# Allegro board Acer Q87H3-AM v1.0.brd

Outline 244 x 244 mm; copper layers: TOP, PWR, GND, BOTTOM. Coordinates in mm from the lower left corner of the outline.
Outline path: 0,240.95 arc(0.89,243.11) 3.05,244 240.95,244 arc(243.11,243.11) 244,240.95 244,3.05 arc(243.11,0.89) 240.95,0 3.05,0 arc(0.89,0.89) 0,3.05 0,240.95

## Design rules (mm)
net group DIFFPAIR133: nets M_CLK_A_N3 M_CLK_A_P3
net group DIFFPAIR134: nets M_CLK_A_N2 M_CLK_A_P2
net group DIFFPAIR135: nets M_CLK_A_N1 M_CLK_A_P1
net group DIFFPAIR136: nets M_CLK_A_N0 M_CLK_A_P0
net group DIFFPAIR197: nets DDIB_AUX_N DDIB_AUX_P
net group DIFFPAIR198: nets DDIB_AUXN DDIB_AUXP
net group DIFFPAIR199: nets DDIB_AUXN_C DDIB_AUXP_C
net group DIFFPAIR237: nets USB_N10 USB_P10
net group DIFFPAIR245: nets BRIDGE_CLK_N BRIDGE_CLK_P
net group DIFFPAIR256: nets USB+12 USB-12
net group DIFFPAIR257: nets USB+13 USB-13
net group DIFFPAIR259: nets DDIC_N0_R DDIC_P0_R
net group DIFFPAIR260: nets DDIC_N1_R DDIC_P1_R
net group DIFFPAIR261: nets DDIC_N2_R DDIC_P2_R
net group DIFFPAIR262: nets DDIC_N3_R DDIC_P3_R
net group DIFFPAIR264: nets ISEN1_3 V3N
net group DIFFPAIR265: nets ISEN1_2 V2N
net group DIFFPAIR266: nets ISEN1_1 V1N
net group DIFFPAIR267: nets ISEN1_4 V4N
net group DIFFPAIR269: nets SATA3_TX_N1_C SATA3_TX_P1_C
net group DIFFPAIR270: nets SATA3_RX_N1_C SATA3_RX_P1_C
net group DIFFPAIR271: nets SATA3_TX_N3_C SATA3_TX_P3_C
net group DIFFPAIR272: nets SATA3_RX_N3_C SATA3_RX_P3_C
net group DIFFPAIR273: nets SATA3_TX_N0_C SATA3_TX_P0_C
net group DIFFPAIR274: nets SATA3_RX_N0_C SATA3_RX_P0_C
net group DIFFPAIR275: nets SATA3_TX_N2_C SATA3_TX_P2_C
net group DIFFPAIR276: nets SATA3_RX_N2_C SATA3_RX_P2_C
net group DIFFPAIR277: nets +VCC_CSN2 +VCC_CSP2
net group DIFFPAIR278: nets +VCC3_CSN1 +VCC3_CSP1
net group DIFFPAIR279: nets DDIC_AUXN DDIC_AUXP
net group DIFFPAIR280: nets USB+3 USB-3
net group DIFFPAIR281: nets ILAN_TXN_C ILAN_TXP_C
net group DIFFPAIR282: nets ILAN_RXN_C ILAN_RXP_C
net group DIFFPAIR283: nets BRIDGE_TX_N2 BRIDGE_TX_P2
net group DIFFPAIR284: nets BRIDGE_TX_N2_C BRIDGE_TX_P2_C
net group DIFFPAIR285: nets BRIDGE_RX_N2_C BRIDGE_RX_P2_C
net group DIFFPAIR286: nets BRIDGE_RX_N2 BRIDGE_RX_P2
net group DIFFPAIR287: nets DDIC_AUX_N DDIC_AUX_P
net group DIFFPAIR288: nets RLAN_RXN_C RLAN_RXP_C
net group DIFFPAIR289: nets RLAN_TXN_C RLAN_TXP_C
net group DIFFPAIR292: nets SATA3_RX_N4_C SATA3_RX_P4_C
net group DIFFPAIR293: nets SATA3_TX_N4_C SATA3_TX_P4_C
net group DIFFPAIR294: nets SATA3_RX_N4 SATA3_RX_P4
net group DIFFPAIR295: nets SATA3_TX_N4 SATA3_TX_P4
net group DIFFPAIR296: nets DDIC_AUXN_C DDIC_AUXP_C
net group G1_UG: nets G1_UG G1_UG_R
net group G2_UG: nets G2_UG G2_UG_R
net group G3_UG: nets G3_UG G3_UG_R
net group DDR_DQS_A: nets M_DQS_A_N0 M_DQS_A_N1 M_DQS_A_N2 M_DQS_A_N3 M_DQS_A_N4 M_DQS_A_N5 M_DQS_A_N6 M_DQS_A_N7 M_DQS_A_P0 M_DQS_A_P1 M_DQS_A_P2 M_DQS_A_P3 M_DQS_A_P4 M_DQS_A_P5 M_DQS_A_P6 M_DQS_A_P7
net group DDR_DQS_B: nets M_DQS_B_N0 M_DQS_B_N1 M_DQS_B_N2 M_DQS_B_N3 M_DQS_B_N4 M_DQS_B_N5 M_DQS_B_N6 M_DQS_B_N7 M_DQS_B_P0 M_DQS_B_P1 M_DQS_B_P2 M_DQS_B_P3 M_DQS_B_P4 M_DQS_B_P5 M_DQS_B_P6 M_DQS_B_P7
net group DDRCLK-B: nets M_CLK_B_N0 M_CLK_B_N1 M_CLK_B_N2 M_CLK_B_N3 M_CLK_B_P0 M_CLK_B_P1 M_CLK_B_P2 M_CLK_B_P3
net group DDRCMD-A: nets M_BS_A0 M_BS_A1 M_BS_A2 M_CAS_A_L M_MA_A0 M_MA_A1 M_MA_A2 M_MA_A3 M_MA_A4 M_MA_A5 M_MA_A6 M_MA_A7 M_MA_A8 M_MA_A9 M_MA_A10 M_MA_A11 M_MA_A12 M_MA_A13 M_MA_A14 M_MA_A15 M_RAS_A_L M_WE_A_L
net group DDRCMD-B: nets M_BS_B0 M_BS_B1 M_BS_B2 M_CAS_B_L M_MA_B0 M_MA_B1 M_MA_B2 M_MA_B3 M_MA_B4 M_MA_B5 M_MA_B6 M_MA_B7 M_MA_B8 M_MA_B9 M_MA_B10 M_MA_B11 M_MA_B12 M_MA_B13 M_MA_B14 M_MA_B15 M_RAS_B_L M_WE_B_L
net group DDRCTRL-A: nets M_CKE_A0 M_CKE_A1 M_CKE_A2 M_CKE_A3 M_CS_A_L0 M_CS_A_L1 M_CS_A_L2 M_CS_A_L3 M_ODT_A0 M_ODT_A1 M_ODT_A2 M_ODT_A3
net group DDRCTRL-B: nets M_CKE_B0 M_CKE_B1 M_CKE_B2 M_CKE_B3 M_CS_B_L0 M_CS_B_L1 M_CS_B_L2 M_CS_B_L3 M_ODT_B0 M_ODT_B1 M_ODT_B2 M_ODT_B3
net group DIFFPAIR268: nets VRD_THERMDC
net group DMI: nets DMI_RX_N0 DMI_RX_N1 DMI_RX_N2 DMI_RX_N3 DMI_RX_P0 DMI_RX_P1 DMI_RX_P2 DMI_RX_P3 DMI_TX_N0 DMI_TX_N1 DMI_TX_N2 DMI_TX_N3 DMI_TX_P0 DMI_TX_P1 DMI_TX_P2 DMI_TX_P3
net group DP: nets DDIB_N0_C DDIB_N0_R DDIB_N1_C DDIB_N1_R DDIB_N2_C DDIB_N2_R DDIB_N3_C DDIB_N3_R DDIB_P0_C DDIB_P0_R DDIB_P1_C DDIB_P1_R DDIB_P2_C DDIB_P2_R DDIB_P3_C DDIB_P3_R DDIB_TX_N0 DDIB_TX_N1 DDIB_TX_N2 DDIB_TX_N3 DDIB_TX_P0 DDIB_TX_P1 DDIB_TX_P2 DDIB_TX_P3 DDIC_N0_C DDIC_N1_C DDIC_N2_C DDIC_N3_C DDIC_P0_C DDIC_P1_C DDIC_P2_C DDIC_P3_C DDIC_TX_N0 DDIC_TX_N1 DDIC_TX_N2 DDIC_TX_N3 DDIC_TX_P0 DDIC_TX_P1 DDIC_TX_P2 DDIC_TX_P3 DDID_N0_C DDID_N1_C DDID_N2_C DDID_N3_C DDID_P0_C DDID_P1_C DDID_P2_C DDID_P3_C DDID_TX_N0 DDID_TX_N1 DDID_TX_N2 DDID_TX_N3 DDID_TX_P0 DDID_TX_P1 DDID_TX_P2 DDID_TX_P3 DVI_CLK_DN_C DVI_CLK_DP_C DVI_TX0_DN_C DVI_TX0_DP_C DVI_TX1_DN_C DVI_TX1_DP_C DVI_TX2_DN_C DVI_TX2_DP_C
net group FDI: nets FDI_TX_N0 FDI_TX_N1 FDI_TX_P0 FDI_TX_P1
net group LG: nets G1_LG G2_LG G3_LG G4_LG LGATE1 LGATE2 LGATE3 LGATE4
net group M_DATA_A: nets M_DATA_A0 M_DATA_A1 M_DATA_A2 M_DATA_A3 M_DATA_A4 M_DATA_A5 M_DATA_A6 M_DATA_A7 M_DATA_A8 M_DATA_A9 M_DATA_A10 M_DATA_A11 M_DATA_A12 M_DATA_A13 M_DATA_A14 M_DATA_A15 M_DATA_A16 M_DATA_A17 M_DATA_A18 M_DATA_A19 M_DATA_A20 M_DATA_A21 M_DATA_A22 M_DATA_A23 M_DATA_A24 M_DATA_A25 M_DATA_A26 M_DATA_A27 M_DATA_A28 M_DATA_A29 M_DATA_A30 M_DATA_A31 M_DATA_A32 M_DATA_A33 M_DATA_A34 M_DATA_A35 M_DATA_A36 M_DATA_A37 M_DATA_A38 M_DATA_A39 M_DATA_A40 M_DATA_A41 M_DATA_A42 M_DATA_A43 M_DATA_A44 M_DATA_A45 M_DATA_A46 M_DATA_A47 M_DATA_A48 M_DATA_A49 M_DATA_A50 M_DATA_A51 M_DATA_A52 M_DATA_A53 M_DATA_A54 M_DATA_A55 M_DATA_A56 M_DATA_A57 M_DATA_A58 M_DATA_A59 M_DATA_A60 M_DATA_A61 M_DATA_A62 M_DATA_A63
net group M_DATA_B: nets M_DATA_B0 M_DATA_B1 M_DATA_B2 M_DATA_B3 M_DATA_B4 M_DATA_B5 M_DATA_B6 M_DATA_B7 M_DATA_B8 M_DATA_B9 M_DATA_B10 M_DATA_B11 M_DATA_B12 M_DATA_B13 M_DATA_B14 M_DATA_B15 M_DATA_B16 M_DATA_B17 M_DATA_B18 M_DATA_B19 M_DATA_B20 M_DATA_B21 M_DATA_B22 M_DATA_B23 M_DATA_B24 M_DATA_B25 M_DATA_B26 M_DATA_B27 M_DATA_B28 M_DATA_B29 M_DATA_B30 M_DATA_B31 M_DATA_B32 M_DATA_B33 M_DATA_B34 M_DATA_B35 M_DATA_B36 M_DATA_B37 M_DATA_B38 M_DATA_B39 M_DATA_B40 M_DATA_B41 M_DATA_B42 M_DATA_B43 M_DATA_B44 M_DATA_B45 M_DATA_B46 M_DATA_B47 M_DATA_B48 M_DATA_B49 M_DATA_B50 M_DATA_B51 M_DATA_B52 M_DATA_B53 M_DATA_B54 M_DATA_B55 M_DATA_B56 M_DATA_B57 M_DATA_B58 M_DATA_B59 M_DATA_B60 M_DATA_B61 M_DATA_B62 M_DATA_B63
net group MDI: nets I_MDI0N I_MDI0P I_MDI1N I_MDI1P I_MDI2N I_MDI2P I_MDI3N I_MDI3P MDI0N MDI0P MDI1N MDI1P MDI2N MDI2P MDI3N MDI3P
net group PCH-CLK: nets BRIDGE_100M_N BRIDGE_100M_P CK_DMI_100M_N CK_DMI_100M_P CK_DP_NSSC_N CK_DP_NSSC_P CK_DP_SSC_N CK_DP_SSC_P CK_H_XDP_N CK_H_XDP_P ILAN_CLKN ILAN_CLKP PEX1_100M_N PEX1_100M_P PEX4_100M_N PEX4_100M_P PEX16_100M_N PEX16_100M_P RLAN_CLKN RLAN_CLKP
net group PCH-PCIE: nets GLAN_RX_N3 GLAN_RX_P3 GLAN_TX_N3 GLAN_TX_P3 ILAN_RXN ILAN_RXP ILAN_TXN ILAN_TXP RLAN_RXN RLAN_RXP RLAN_TXN RLAN_TXP
net group PCIE: nets HSODN4 HSODN5 HSODN6 HSODN7 HSODN8 HSODP4 HSODP5 HSODP6 HSODP7 HSODP8 PEX1_RX_N4 PEX1_RX_P4 PEX1_TX_N4 PEX1_TX_P4 PEX4_RX_N5 PEX4_RX_N6 PEX4_RX_N7 PEX4_RX_N8 PEX4_RX_P5 PEX4_RX_P6 PEX4_RX_P7 PEX4_RX_P8 PEX4_TX_N5 PEX4_TX_N6 PEX4_TX_N7 PEX4_TX_N8 PEX4_TX_P5 PEX4_TX_P6 PEX4_TX_P7 PEX4_TX_P8
net group PCIE-16X: nets PEG_RX_N0 PEG_RX_N1 PEG_RX_N2 PEG_RX_N3 PEG_RX_N4 PEG_RX_N5 PEG_RX_N6 PEG_RX_N7 PEG_RX_N8 PEG_RX_N9 PEG_RX_N10 PEG_RX_N11 PEG_RX_N12 PEG_RX_N13 PEG_RX_N14 PEG_RX_N15 PEG_RX_P0 PEG_RX_P1 PEG_RX_P2 PEG_RX_P3 PEG_RX_P4 PEG_RX_P5 PEG_RX_P6 PEG_RX_P7 PEG_RX_P8 PEG_RX_P9 PEG_RX_P10 PEG_RX_P11 PEG_RX_P12 PEG_RX_P13 PEG_RX_P14 PEG_RX_P15 PEG_TX_C_N0 PEG_TX_C_N1 PEG_TX_C_N2 PEG_TX_C_N3 PEG_TX_C_N4 PEG_TX_C_N5 PEG_TX_C_N6 PEG_TX_C_N7 PEG_TX_C_N8 PEG_TX_C_N9 PEG_TX_C_N10 PEG_TX_C_N11 PEG_TX_C_N12 PEG_TX_C_N13 PEG_TX_C_N14 PEG_TX_C_N15 PEG_TX_C_P0 PEG_TX_C_P1 PEG_TX_C_P2 PEG_TX_C_P3 PEG_TX_C_P4 PEG_TX_C_P5 PEG_TX_C_P6 PEG_TX_C_P7 PEG_TX_C_P8 PEG_TX_C_P9 PEG_TX_C_P10 PEG_TX_C_P11 PEG_TX_C_P12 PEG_TX_C_P13 PEG_TX_C_P14 PEG_TX_C_P15 PEG_TX_N0 PEG_TX_N1 PEG_TX_N2 PEG_TX_N3 PEG_TX_N4 PEG_TX_N5 PEG_TX_N6 PEG_TX_N7 PEG_TX_N8 PEG_TX_N9 PEG_TX_N10 PEG_TX_N11 PEG_TX_N12 PEG_TX_N13 PEG_TX_N14 PEG_TX_N15 PEG_TX_P0 PEG_TX_P1 PEG_TX_P2 PEG_TX_P3 PEG_TX_P4 PEG_TX_P5 PEG_TX_P6 PEG_TX_P7 PEG_TX_P8 PEG_TX_P9 PEG_TX_P10 PEG_TX_P11 PEG_TX_P12 PEG_TX_P13 PEG_TX_P14 PEG_TX_P15
net group PHASE: nets PHASE1 PHASE2 PHASE3 PHASE4 SWN1 SWN2
net group RGB: nets VGA_BLUE VGA_GREEN VGA_RED
net group RLAN: nets R_MDI0N R_MDI0P R_MDI1N R_MDI1P R_MDI2N R_MDI2P R_MDI3N R_MDI3P
net group SATA30: nets SATA3_RX_N0 SATA3_RX_N1 SATA3_RX_N2 SATA3_RX_N3 SATA3_RX_P0 SATA3_RX_P1 SATA3_RX_P2 SATA3_RX_P3 SATA3_TX_N0 SATA3_TX_N1 SATA3_TX_N2 SATA3_TX_N3 SATA3_TX_P0 SATA3_TX_P1 SATA3_TX_P2 SATA3_TX_P3
net group SUB30: nets USB3_RX_N0 USB3_RX_N0_R USB3_RX_N1 USB3_RX_N1_R USB3_RX_N4 USB3_RX_N4_R USB3_RX_N5 USB3_RX_N5_R USB3_RX_P0 USB3_RX_P0_R USB3_RX_P1 USB3_RX_P1_R USB3_RX_P4 USB3_RX_P4_R USB3_RX_P5 USB3_RX_P5_R USB3_TX_N0 USB3_TX_N0_C USB3_TX_N0_R USB3_TX_N1 USB3_TX_N1_C USB3_TX_N1_R USB3_TX_N4 USB3_TX_N4_C USB3_TX_N4_R USB3_TX_N5 USB3_TX_N5_C USB3_TX_N5_R USB3_TX_P0 USB3_TX_P0_C USB3_TX_P0_R USB3_TX_P1 USB3_TX_P1_C USB3_TX_P1_R USB3_TX_P4 USB3_TX_P4_C USB3_TX_P4_R USB3_TX_P5 USB3_TX_P5_C USB3_TX_P5_R
net group THERMDA: nets CASE_THERMDA TS_D- VRD_THERMDA
net group USB20: nets USB+6 USB+7 USB+8 USB+9 USB+10 USB+11 USB-6 USB-7 USB-8 USB-9 USB-10 USB-11 USB_N0 USB_N0_R USB_N1 USB_N1_R USB_N2 USB_N3 USB_N4 USB_N4_R USB_N5 USB_N5_R USB_N6 USB_N7 USB_N8 USB_N9 USB_N11 USB_N12 USB_N13 USB_P0 USB_P0_R USB_P1 USB_P1_R USB_P2 USB_P3 USB_P4 USB_P4_R USB_P5 USB_P5_R USB_P6 USB_P7 USB_P8 USB_P9 USB_P11 USB_P12 USB_P13

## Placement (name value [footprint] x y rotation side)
A1  -  [J2X1]  190.91 5.87 0 top
A2  -  [J2X1]  190.91 8.92 0 top
ATX_12V  -  [ATX_PWR_4P_1]  233.84 193.96 180 top
ATX_POWER  -  [ATX_PWR_12P-RUIYE]  125.64 9.56 0 top
AUDIO  -  [AUDIO_JACK_13P-KORTAK]  96.45 235.84 0 top
BAT1  +  [BATTERY_1]  220.35 94.06 180 top
BIOS_WP  -  [J3X1]  4.55 168.76 270 top
BZ  -  [BUZZER_1]  218.47 115.22 180 top
C1  -  [C0402_1]  221.52 131.86 180 top
C2  -  [C0402_1]  198.38 127.11 0 top
C3  -  [C0402_1]  198.28 137.83 0 top
C4  -  [C0402_1]  209.94 121.6 270 top
C6  -  [C0603_1]  228.25 129.57 270 top
C7  -  [C0402_1]  207.17 121.7 90 top
C8  -  [C0402_1]  208.31 121.7 90 top
C9  -  [C0402_1]  173.01 76.49 180 top
C10  -  [C0805_1]  167.42 127.67 0 top
C11  -  [C0805_1]  151.29 129.7 0 top
C12  -  [C0805_1]  167.42 131.73 0 top
C15  -  [C0805_1]  163.23 127.67 180 top
C16  -  [C0805_1]  159.16 127.67 0 top
C17  -  [C0805_1]  163.23 131.73 180 top
C18  -  [C0805_1]  159.16 125.64 0 top
C19  -  [C0805_1]  155.1 125.64 180 top
C20  -  [C0805_1]  163.23 129.7 180 top
C21  -  [C0805_1]  159.16 131.73 0 top
C22  -  [C0805_1]  167.42 129.7 0 top
C23  -  [C0805_1]  159.16 129.7 0 top
C24  -  [C0805_1]  155.1 129.7 180 top
C25  -  [C0805_1]  155.1 131.73 180 top
C26  -  [C0805_1]  151.29 131.73 0 top
C27  -  [C0805_1]  155.1 127.67 180 top
C28  -  [C0805_1]  151.29 127.67 0 top
C29  -  [C0805_1]  163.23 125.64 180 top
C30  -  [C0805_1]  168.18 122.97 270 top
C31  -  [C0805_1]  161.83 122.97 270 top
C32  -  [C0805_1]  166.15 122.97 270 top
C33  -  [C0805_1]  153.19 122.97 270 top
C34  -  [C0805_1]  157.51 122.97 270 top
C35  -  [C0805_1]  155.23 122.97 270 top
C36  -  [C0805_1]  163.86 122.97 270 top
C37  -  [C0805_1]  159.54 122.97 270 top
C38  -  [C0805_1]  150.91 122.97 270 top
C39  -  [C0805_1]  165.26 154.59 180 top
C40  -  [C0805_1]  169.96 154.59 180 top
C41  -  [C0805_1]  160.69 154.59 180 top
C42  -  [C0805_1]  174.4 154.59 180 top
C43  -  [C0805_1]  142.53 58.07 90 top
C44  -  [C0805_1]  153.45 58.07 270 top
C45  -  [C0805_1]  159.67 58.07 90 top
C46  -  [C0805_1]  161.7 58.07 270 top
C47  -  [C0402_1]  88.3 181.96 0 top
C48  -  [C0402_1]  55.28 195.1 270 top
C49  -  [C0402_1]  88.3 177.96 0 top
C50  -  [C0402_1]  87.15 186.85 0 top
C51  -  [C0402_1]  88.3 183.17 0 top
C52  -  [C0402_1]  75.98 189.9 90 top
C53  -  [C0402_1]  75.98 191.93 90 top
C54  -  [C0402_1]  87.15 188.25 0 top
C55  -  [C0402_1]  75.98 196.25 270 top
C56  -  [C0402_1]  88.3 179.17 0 top
C57  -  [C0402_1]  88.3 173.96 0 top
C58  -  [C0402_1]  88.3 175.1 0 top
C59  -  [C0402_1]  88.3 169.96 0 top
C60  -  [C0402_1]  88.3 171.1 0 top
C61  -  [C0402_1]  88.3 163.99 0 top
C62  -  [C0402_1]  88.3 165.13 0 top
C63  -  [C0402_1]  88.3 159.93 0 top
C64  -  [C0402_1]  88.3 161.07 0 top
C65  -  [C0402_1]  88.3 155.99 0 top
C66  -  [C0402_1]  88.3 157.13 0 top
C67  -  [C0402_1]  88.3 151.99 0 top
C68  -  [C0402_1]  88.3 153.13 0 top
C69  -  [C0402_1]  88.3 146.02 0 top
C70  -  [C0402_1]  88.3 147.16 0 top
C71  -  [C0402_1]  88.3 141.89 0 top
C72  -  [C0402_1]  88.3 143.03 0 top
C73  -  [C0402_1]  88.3 138.02 0 top
C74  -  [C0402_1]  88.3 139.16 0 top
C75  -  [C0402_1]  88.3 134.02 0 top
C76  -  [C0402_1]  88.3 135.16 0 top
C77  -  [C0402_1]  88.3 130.02 0 top
C78  -  [C0402_1]  88.3 131.16 0 top
C79  -  [C0402_1]  88.3 126.02 0 top
C80  -  [C0402_1]  88.3 127.16 0 top
C81  -  [C0402_1]  88.3 121.95 0 top
C82  -  [C0402_1]  88.3 123.1 0 top
C83  -  [C0402_1]  88.3 119.16 0 top
C84  -  [C0402_1]  88.3 118.02 0 top
C85  -  [C0402_1]  208.06 214.79 90 top
C86  -  [C0402_1]  209.2 214.79 90 top
C87  -  [C0402_1]  210.09 212.63 90 top
C88  -  [C0402_1]  211.23 212.63 90 top
C89  -  [C0402_1]  212.12 214.79 90 top
C90  -  [C0402_1]  213.27 214.79 90 top
C91  -  [C0402_1]  215.3 212.63 90 top
C92  -  [C0402_1]  214.15 212.63 90 top
C93  -  [C0402_1]  220.38 209.33 90 top
C94  -  [C0402_1]  221.65 209.33 90 top
C95  -  [C0402_1]  228.76 223.17 270 top
C98  -  [C0402_1]  184.94 218.98 90 top
C99  -  [C0402_1]  183.8 218.98 90 top
C100  -  [C0402_1]  181.64 218.98 90 top
C101  -  [C0402_1]  180.5 218.98 90 top
C102  -  [C0402_1]  183.29 221.14 90 top
C103  -  [C0402_1]  182.15 221.14 90 top
C104  -  [C0402_1]  186.09 221.14 90 top
C105  -  [C0402_1]  187.23 221.14 90 top
C107  -  [C0402_1]  190.28 222.28 180 top
C108  -  [C0402_1]  177.71 210.85 90 top
C109  -  [C0402_1]  175.67 208.69 90 top
C110  -  [C0402_1]  173.77 210.85 90 top
C111  -  [C0402_1]  172.63 210.85 90 top
C112  -  [C0402_1]  176.56 210.85 90 top
C113  -  [C0402_1]  174.53 208.69 90 top
C114  -  [C0402_1]  178.59 208.69 90 top
C115  -  [C0402_1]  179.74 208.69 90 top
C116  -  [C0603_1]  148.24 212.63 270 top
C117  -  [C0402_1]  153.07 215.42 180 top
C118  -  [C0402_1]  158.66 215.42 180 top
C119  -  [C0402_1]  155.86 215.42 180 top
C120  -  [C0402_1]  158.27 217.96 180 top
C121  -  [C0402_1]  155.73 217.96 0 top
C122  -  [C0402_1]  153.58 217.96 180 top
C123  -  [C0402_1]  158.02 212.88 0 top
C125  -  [C0402_1]  155.23 212.88 0 top
C126  -  [C0402_1]  152.43 212.88 0 top
C127  -  [C0402_1]  161.45 214.92 180 top
C128  -  [C0402_1]  163.74 214.92 180 top
C129  -  [C0402_1]  150.02 222.16 180 top
C130  -  [C0402_1]  163.94 76.99 90 top
C131  -  [C0402_1]  145.96 76.97 90 top
C132  -  [C0402_1]  152.1 77.02 90 top
C133  -  [C0402_1]  139.94 76.99 90 top
C134  -  [C0402_1]  157.92 76.97 90 top
C135  -  [C0805_1]  90.58 57.69 270 top
C136  -  [C0402_1]  97.7 56.47 180 top
C137  -  [C0805_1]  88.68 57.69 270 top
C138  -  [C0402_1]  97.7 57.56 180 top
C139  -  [C0402_1]  100.87 59.09 180 top
C140  -  [C0402_1]  100.87 56.8 180 top
C141  -  [C0402_1]  164.88 46.9 270 top
C142  -  [C0402_1]  145.19 36.99 0 top
C143  -  [C0402_1]  145.45 57.03 180 top
C144  -  [C0603_1]  168.82 57.95 90 top
C145  -  [C0603_1]  143.42 36.23 270 top
C146  -  [C0402_1]  153.83 36.99 0 top
C147  -  [C0402_1]  147.35 36.99 0 top
C148  -  [C0402_1]  149.51 36.99 0 top
C149  -  [C0603_1]  169.32 36.99 180 top
C150  -  [C0603_1]  167.42 57.95 90 top
C151  -  [C0402_1]  151.67 36.99 0 top
C152  -  [C0402_1]  148.88 46.9 270 top
C153  -  [C0402_1]  152.43 46.9 90 top
C154  -  [C0603_1]  138.59 57.36 90 top
C155  -  [C0402_1]  155.99 36.99 0 top
C156  -  [C0402_1]  158.15 36.99 0 top
C157  -  [C0402_1]  160.31 36.99 0 top
C158  -  [C0603_1]  139.99 57.36 90 top
C159  -  [C0805_1]  92.49 57.69 270 top
C160  -  [C0402_1]  97.57 59.16 270 top
C161  -  [C0805_1]  94.39 57.69 270 top
C162  -  [C0402_1]  95.92 58.58 270 top
C163  -  [C0402_1]  162.59 36.99 180 top
C164  -  [C0402_1]  140.49 59.34 180 top
C165  -  [C0402_1]  155.46 56.45 180 top
C166  -  [C0402_1]  166.02 58.83 270 top
C167  -  [C0402_1]  158.91 46.9 270 top
C168  -  [C0603_1]  165.26 36.99 0 top
C169  -  [C0402_1]  155.48 59.21 180 top
C170  -  [C0402_1]  157.39 57.06 90 top
C171  -  [C0402_1]  141 46.9 270 top
C172  -  [C0402_1]  164.75 56.55 0 top
C173  -  [C0402_1]  146.84 46.9 270 top
C174  -  [C0402_1]  158.15 59.09 270 top
C175  -  [C0402_1]  151.42 56.42 180 top
C176  -  [C0402_1]  154.72 46.9 270 top
C177  -  [C0402_1]  144.56 58.71 90 top
C178  -  [C0402_1]  132.49 36.61 90 top
C179  -  [C0402_1]  151.04 58.71 270 top
C180  -  [C0402_1]  142.22 36.61 270 top
C181  -  [C0402_1]  214.1 59.11 270 top
C182  -  [C0402_1]  214.08 57 90 top
C183  -  [C0402_1]  217.51 59.14 90 top
C184  -  [C0402_1]  217.51 57 270 top
C185  -  [C0402_1]  223.7 59.11 270 top
C186  -  [C0402_1]  224.85 59.11 270 top
C187  -  [C0402_1]  224.85 57 90 top
C188  -  [C0402_1]  223.7 57 90 top
C189  -  [C0402_1]  170.15 222.22 0 top
C190  -  [C0402_1]  43.72 115.98 270 top
C191  -  [C0402_1]  42.58 115.98 270 top
C192  -  [C0402_1]  44.86 115.98 270 top
C193  -  [C0402_1]  29.5 110.4 180 top
C194  -  [C0402_1]  29.88 107.98 180 top
C195  -  [C0402_1]  32.8 119.29 180 top
C196  -  [C0402_1]  29.88 111.67 180 top
C197  -  [C0402_1]  29.88 106.71 180 top
C198  -  [C0402_1]  61.37 123.73 0 top
C199  -  [C0402_1]  58.58 123.73 180 top
C200  -  [C0402_1]  25.05 36.61 0 top
C201  -  [C0402_1]  34.7 14.76 0 top
C202  -  [C0402_1]  25.05 37.75 0 top
C203  -  [C0402_1]  34.7 15.91 0 top
C204  -  [C0402_1]  25.05 40.42 0 top
C205  -  [C0402_1]  34.7 20.35 0 top
C206  -  [C0402_1]  25.05 41.56 0 top
C207  -  [C0402_1]  34.7 21.5 0 top
C208  -  [C0402_1]  160.36 210.98 270 top
C209  -  [C0402_1]  34.07 17.18 180 top
C210  -  [C0402_1]  165.77 211.36 270 top
C211  -  [C0402_1]  34.07 18.32 180 top
C213  -  [C0402_1]  34.07 24.04 180 top
C215  -  [C0402_1]  34.07 25.18 180 top
C217  -  [C0402_1]  34.55 33.03 0 top
C219  -  [C0402_1]  34.55 34.17 0 top
C221  -  [C0402_1]  34.55 40.39 0 top
C223  -  [C0402_1]  34.55 41.54 0 top
C224  -  [C0402_1]  63.28 81.82 180 top
C225  -  [C0402_1]  22.32 71.41 0 top
C226  -  [C0402_1]  9.38 159.62 180 top
C227  -  [C0402_1]  9.81 163.48 90 top
C228  -  [C0603_1]  12.75 167.75 0 top
C229  -  [C0402_1]  9.43 155.35 180 top
C230  -  [C0402_1]  33.31 79.92 270 top
C231  -  [C0402_1]  18.19 67.47 180 top
C232  -  [C0402_1]  18.19 66.33 180 top
C233  -  [C0402_1]  34.07 64.55 0 top
C234  -  [C0402_1]  35.59 65.69 270 top
C235  -  [C0402_1]  24.42 68.87 0 top
C236  -  [C0402_1]  24.42 67.47 0 top
C237  -  [C0603_1]  7.53 67.72 0 top
C238  -  [C0603_1]  6.76 69.88 90 top
C239  -  [C0402_1]  28.25 78.42 0 top
C240  -  [C0603_1]  35.11 79.79 90 top
C241  -  [C0805_1]  35.9 63.02 180 top
C242  -  [C0402_1]  30.36 78.42 180 top
C243  -  [C0805_1]  63.02 75.93 90 top
C244  -  [C0805_1]  67.22 104.68 270 top
C245  -  [C0402_1]  165.77 208.57 90 top
C246  -  [C0402_1]  160.36 208.82 90 top
C247  -  [C0402_1]  39.28 70.77 180 top
C248  -  [C0603_1]  70.26 72.93 270 top
C249  -  [C0402_1]  52.74 77.44 270 top
C250  -  [C0402_1]  55.91 112.94 180 top
C251  -  [C0402_1]  51.96 74.71 270 top
C252  -  [C0402_1]  39.15 116.24 90 top
C253  -  [C0603_1]  58.45 113.06 180 top
C254  -  [C0402_1]  28.1 100.49 0 top
C255  -  [C0805_1]  45.75 119.41 270 top
C256  -  [C0402_1]  46.13 115.98 90 top
C257  -  [C0603_1]  66.33 107.6 180 top
C258  -  [C0603_1]  72.8 89.44 270 top
C259  -  [C0603_1]  47.53 117.38 90 top
C260  -  [C0603_1]  69.25 107.6 0 top
C261  -  [C0603_1]  29.62 114.71 180 top
C262  -  [C0402_1]  48.61 80.04 270 top
C263  -  [C0603_1]  29.62 113.32 180 top
C264  -  [C0402_1]  49.69 80.04 270 top
C268  -  [C0603_1]  68.87 104.93 270 top
C269  -  [C0603_1]  68.74 72.93 270 top
C270  -  [C0603_1]  72.3 72.93 270 top
C271  -  [C0603_1]  72.8 94.01 270 top
C273  -  [C0603_1]  51.59 79.73 270 top
C278  -  [C0805_1]  68.99 69.63 90 top
C279  -  [C0603_1]  67.34 69.37 90 top
C280  -  [C0603_1]  65.95 69.37 90 top
C281  -  [C0402_1]  24.42 80.42 180 top
C282  -  [C0402_1]  22.77 80.8 270 top
C283  -  [C0603_1]  32.16 76.74 270 top
C284  -  [C0402_1]  65.44 86.52 0 top
C285  -  [C0402_1]  65.44 85.38 0 top
C286  -  [C0603_1]  65.82 87.79 0 top
C287  -  [C0402_1]  27.21 82.58 180 top
C289  -  [C0402_1]  26.32 183.04 0 top
C290  -  [C0402_1]  54.64 178.98 270 top
C291  -  [C0402_1]  26.32 181.9 0 top
C292  -  [C0402_1]  55.66 178.98 270 top
C293  -  [C0402_1]  26.32 179.1 0 top
C294  -  [C0402_1]  26.32 177.96 0 top
C295  -  [C0402_1]  26.32 174.02 0 top
C296  -  [C0402_1]  26.32 175.17 0 top
C297  -  [C0402_1]  26.32 170.97 0 top
C298  -  [C0402_1]  26.32 169.83 0 top
C299  -  [C0402_1]  26.32 184.94 0 top
C300  -  [C0402_1]  55.66 189.9 90 top
C301  -  [C0402_1]  25.94 190.02 90 top
C302  -  [C0402_1]  55.66 191.93 90 top
C303  -  [C0402_1]  66.2 196.25 270 top
C304  -  [C0402_1]  25.69 199.42 90 top
C305  -  [C0402_1]  66.2 188.88 90 top
C306  -  [C0402_1]  55.53 183.04 270 top
C307  -  [C0402_1]  66.58 191.93 90 top
C308  -  [C0402_1]  53.75 200.82 0 top
C309  -  [C0402_1]  35.59 200.18 90 top
C310  -  [C0402_1]  66.2 186.34 90 top
C324  -  [C0805_1]  61.25 160.56 270 top
C325  -  [C0603_1]  59.6 160.81 270 top
C326  -  [C0402_1]  54.13 159.8 90 top
C327  -  [C0805_1]  72.04 147.91 0 top
C328  -  [C0603_1]  71.79 149.56 0 top
C329  -  [C0402_1]  68.89 147.23 90 top
C330  -  [C0402_1]  69.12 139.35 0 top
C331  -  [C0805_1]  66.96 159.67 90 top
C332  -  [C0603_1]  65.31 159.42 90 top
C333  -  [C0402_1]  55.66 137.45 270 top
C334  -  [C0402_1]  60.23 138.59 90 top
C335  -  [C0805_1]  72.55 140.37 270 top
C336  -  [C0603_1]  70.9 140.62 270 top
C337  -  [C0402_1]  69.63 141 270 top
C338  -  [C0402_1]  74.58 147.99 90 top
C339  -  [C0402_1]  71.41 144.05 0 top
C340  -  [C0805_1]  63.02 164.88 90 top
C341  -  [C0603_1]  56.93 137.19 270 top
C342  -  [C0402_1]  63.41 160.05 90 top
C343  -  [C0402_1]  69.76 153.96 180 top
C344  -  [C0402_1]  69.76 155.1 180 top
C345  -  [C0402_1]  50.96 137.45 270 top
C346  -  [C0402_1]  47.53 182.02 180 top
C347  -  [C0402_1]  34.83 182.02 270 top
C348  -  [C0402_1]  47.28 169.45 0 top
C349  -  [C0402_1]  54.26 161.96 90 top
C350  -  [C0402_1]  47.28 191.93 270 top
C351  -  [C0402_1]  47.4 197.39 0 top
C352  -  [C0402_1]  37.55 207.17 0 top
C353  -  [C0402_1]  26.83 199.42 90 top
C354  -  [C0402_1]  46.64 187.46 90 top
C355  -  [C0402_1]  14.26 129.19 0 top
C356  -  [C0402_1]  7.78 122.21 0 top
C357  -  [C0402_1]  4.48 121.19 180 top
C358  -  [C0402_1]  4.48 99.35 180 top
C359  -  [C0402_1]  4.48 98.2 180 top
C360  -  [C0402_1]  139.73 218.73 0 top
C361  -  [C0402_1]  137.19 218.22 270 top
C362  -  [C0402_1]  142.78 226.22 0 top
C364  -  [C0402_1]  33.56 53.12 180 top
C365  -  [C0402_1]  33.56 54.26 180 top
C366  -  [C0402_1]  33.56 55.4 180 top
C367  -  [C0402_1]  33.56 56.55 180 top
C368  -  [C0402_1]  14.64 38.51 270 top
C369  -  [C0402_1]  25.31 61.12 0 top
C370  -  [C0805_1]  17.43 4.73 90 top
C371  -  [C0402_1]  19.08 4.6 90 top
C372  -  [C0805_1]  30.13 4.78 90 top
C373  -  [C0402_1]  31.66 4.22 90 top
C374  -  [C0402_1]  218.92 12.92 270 top
C375  -  [C0402_1]  221.46 11.91 270 top
C376  -  [C0402_1]  226.54 13.18 270 top
C377  -  [C0402_1]  225.14 13.18 270 top
C378  -  [C0402_1]  223.68 12.99 270 top
C379  -  [C0402_1]  222.54 12.61 270 top
C380  -  [C0603_1]  216.63 12.73 90 top
C381  -  [C0603_1]  228.7 12.29 180 top
C382  -  [C0805_1]  229.39 10.45 180 top
C383  -  [C0402_1]  212.12 13.75 180 top
C384  -  [C0402_1]  205.65 35.59 90 top
C385  -  [C0402_1]  212.12 12.61 0 top
C386  -  [C0603_1]  202.72 11.21 0 top
C387  -  [C0402_1]  221.14 35.85 270 top
C388  -  [C0402_1]  204.48 35.62 90 top
C389  -  [C0603_1]  203.23 35.24 90 top
C390  -  [C0603_1]  199.3 25.43 180 top
C391  -  [C0402_1]  219.62 35.85 90 top
C392  -  [C0402_1]  218.47 35.85 90 top
C393  -  [C0402_1]  198.91 26.65 180 top
C394  -  [C0402_1]  210.73 35.34 0 top
C395  -  [C0402_1]  206.79 35.59 90 top
C396  -  [C0402_1]  200.44 13.37 270 top
C397  -  [C0805_1]  198.91 12.99 270 top
C398  -  [C0402_1]  199.17 32.42 270 top
C399  -  [C0402_1]  199.55 29.88 90 top
C400  -  [C0402_1]  199.17 22.94 180 top
C401  -  [C0402_1]  68.49 110.01 270 top
C402  -  [C0402_1]  66.2 110.01 270 top
C403  -  [C0402_1]  63.15 113.06 180 top
C404  -  [C0402_1]  60.99 113.06 180 top
C405  -  [C0402_1]  14.26 125.76 0 top
C406  -  [C0402_1]  235.36 101.38 180 top
C407  -  [C0805_1]  115.09 189.52 90 top
C408  -  [C0402_1]  110.65 174.02 270 top
C409  -  [C0402_1]  238.41 223.55 0 top
C410  -  [C0402_1]  225.58 106.59 90 top
C411  -  [C0402_1]  233.71 100.87 90 top
C412  -  [C0402_1]  231.93 223.17 270 top
C413  -  [C0402_1]  233.33 223.17 270 top
C414  -  [C0402_1]  234.73 223.17 270 top
C415  -  [C0402_1]  236.13 223.17 270 top
C417  -  [C0603_1]  9.81 43.21 180 top
C418  -  [C0402_1]  181.77 12.86 270 top
C419  -  [C0402_1]  151.8 12.22 90 top
C420  -  [C0402_1]  6.38 139.61 270 top
C422  -  [C0402_1]  232.44 27.59 90 top
C423  -  [C0402_1]  235.94 27.34 90 top
C425  -  [C0805_1]  239.94 16.54 90 top
C426  -  [C0402_1]  231.11 16.23 90 top
C427  -  [C0805_1]  236.51 16.29 90 top
C428  -  [C0402_1]  238.03 16.54 90 top
C429  -  [C0402_1]  232.44 29.75 270 top
C431  -  [C0402_1]  195.36 6.05 90 top
C432  -  [C0402_1]  225.97 7.4 270 top
C433  -  [C0402_1]  224.14 7.4 270 top
C434  -  [C0402_1]  209.2 10.38 270 top
C435  -  [C0402_1]  207.42 203.87 90 top
C436  -  [C0402_1]  225.33 3.59 0 top
C437  -  [C0402_1]  67.09 221.27 270 top
C438  -  [C0402_1]  62.52 221.39 0 top
C439  -  [C0402_1]  62.52 220.25 0 top
C440  -  [C0402_1]  62.52 219.11 0 top
C441  -  [C0402_1]  62.52 217.96 0 top
C442  -  [C0603_1]  72.42 220.89 270 top
C443  -  [C0805_1]  79.28 207.68 270 top
C444  -  [C0402_1]  75.85 206.66 270 top
C445  -  [C0402_1]  60.87 209.33 0 top
C446  -  [C0402_1]  58.33 209.33 180 top
C447  -  [C0805_1]  77.38 207.68 270 top
C448  -  [C0402_1]  43.72 217.84 0 top
C449  -  [C0402_1]  47.15 217.84 180 top
C450  -  [C0402_1]  20.1 206.66 0 top
C451  -  [C0805_1]  21.56 202.66 180 top
C452  -  [C0402_1]  48.29 221.27 90 top
C453  -  [C0402_1]  43.72 224.57 0 top
C455  -  [C0402_1]  51.85 221.27 90 top
C456  -  [C0402_1]  43.72 232.44 0 top
C457  -  [C0402_1]  59.21 234.6 180 top
C458  -  [C0402_1]  58.58 225.84 180 top
C459  -  [C0805_1]  55.79 220.89 180 top
C460  -  [C0402_1]  55.15 222.41 180 top
C461  -  [C0402_1]  55.66 237.27 270 top
C462  -  [C0805_1]  67.41 225.71 90 top
C463  -  [C0402_1]  67.41 228 0 top
C464  -  [C0402_1]  47.15 221.27 90 top
C465  -  [C0402_1]  59.21 233.59 180 top
C466  -  [C0402_1]  46.01 221.27 90 top
C467  -  [C0402_1]  43.72 231.43 0 top
C468  -  [C0402_1]  54.64 237.27 270 top
C469  -  [C0402_1]  44.97 236.79 270 top
C470  -  [C0402_1]  59.21 232.32 180 top
C471  -  [C0402_1]  50.32 221.27 90 top
C472  -  [C0402_1]  58.58 230.92 180 top
C473  -  [C0402_1]  58.58 227.62 180 top
C474  -  [C0402_1]  48.01 236.79 270 top
C475  -  [C0402_1]  49.03 236.79 270 top
C476  -  [C0402_1]  43.72 225.84 0 top
C477  -  [C0402_1]  43.72 226.85 0 top
C478  -  [C0402_1]  24.29 202.53 270 top
C479  -  [C0402_1]  52.61 237.07 270 top
C480  -  [C0402_1]  51.59 237.07 270 top
C481  -  [C0402_1]  45.98 236.79 90 top
C482  -  [C0402_1]  47 236.79 90 top
C483  -  [C0402_1]  80.04 219.62 180 top
C484  -  [C0603_1]  24.8 81.69 180 top
C486  -  [C0402_1]  65.31 113.06 180 top
C487  -  [C0402_1]  67.34 110.01 270 top
C488  -  [C0402_1]  57.69 74.52 0 top
C489  -  [C0402_1]  59.85 74.52 0 top
C490  -  [C0402_1]  71.28 99.09 0 top
C491  -  [C0402_1]  117.13 215.3 270 top
C492  -  [C0402_1]  58.58 229.01 180 top
C493  -  [C0402_1]  107.86 215.17 90 top
C494  -  [C0402_1]  106.71 215.17 90 top
C495  -  [C0603_1]  100.11 220.89 90 top
C496  -  [C0402_1]  101.25 221.27 270 top
C497  -  [C0402_1]  75.47 99.09 180 top
C498  -  [C0402_1]  73.31 99.09 180 top
C499  -  [C0402_1]  103.97 215.25 90 top
C500  -  [C0402_1]  114.33 206.41 90 top
C501  -  [C0402_1]  113.19 206.41 90 top
C502  -  [C0402_1]  125.89 217.71 180 top
C503  -  [C0402_1]  111.03 203.74 90 top
C504  -  [C0402_1]  112.17 203.74 90 top
C505  -  [C0805_1]  29.37 209.58 270 top
C506  -  [C0402_1]  16.67 230.03 90 top
C507  -  [C0805_1]  21.11 233.33 90 top
C508  -  [C0805_1]  11.08 225.33 90 top
C509  -  [C0402_1]  12.61 225.2 90 top
C510  -  [C0402_1]  21.24 227.87 180 top
C511  -  [C0805_1]  21.24 230.03 90 top
C512  -  [C0805_1]  25.56 228.25 270 top
C513  -  [C0603_1]  11.34 222.92 0 top
C514  -  [C0805_1]  23.53 228.25 270 top
C515  -  [C0805_1]  23.27 233.33 270 top
C516  -  [C0805_1]  25.31 233.33 270 top
C517  -  [C0603_1]  11.34 220.38 0 top
C518  -  [C0805_1]  23.15 238.03 90 top
C519  -  [C0805_1]  25.18 238.03 90 top
C520  -  [C0805_1]  15.53 213.52 270 top
C521  -  [C0805_1]  13.24 212.38 270 top
C522  -  [C0402_1]  13.24 214.66 180 top
C523  -  [C0402_1]  19.97 214.03 270 top
C524  -  [C0402_1]  21.11 214.03 270 top
C525  -  [C0402_1]  17.43 214.03 270 top
C526  -  [C0402_1]  9.84 177.22 90 top
C527  -  [C0805_1]  7.65 181.39 0 top
C528  -  [C0402_1]  9.3 184.56 270 top
C531  -  [C0402_1]  9.3 213.52 270 top
C532  -  [C0402_1]  5.87 213.52 270 top
C533  -  [C0402_1]  4.86 232.57 270 top
C534  -  [C0402_1]  4.86 229.78 270 top
C535  -  [C0402_1]  72.04 237.27 270 top
C536  -  [C0402_1]  84.23 223.55 90 top
C537  -  [C0402_1]  88.17 237.01 270 top
C538  -  [C0402_1]  72.17 239.81 270 top
C540  -  [C0603_1]  97.19 23.65 90 top
C541  -  [C0402_1]  192.06 24.16 270 top
C542  -  [C0805_1]  106.59 30.64 0 top
C543  -  [C0805_1]  104.43 26.83 270 top
C544  -  [C0402_1]  99.35 30.13 90 top
C545  -  [C0805_1]  97.19 27.08 270 top
C546  -  [C0805_1]  180.37 34.2 90 top
C547  -  [C0805_1]  180.37 30.77 270 top
C548  -  [C0603_1]  165.51 23.4 180 top
C549  -  [C0603_1]  189.52 36.61 180 top
C550  -  [C0402_1]  195.36 36.61 0 top
C551  -  [C0603_1]  101.76 31.66 90 top
C552  -  [C0603_1]  170.72 18.19 180 top
C553  -  [C0402_1]  165.87 20.89 180 top
C554  -  [C0402_1]  144.18 29.37 270 top
C555  -  [C0805_1]  145.7 33.18 90 top
C556  -  [C0805_1]  145.7 29.37 270 top
C557  -  [C0402_1]  165.26 18.83 90 top
C558  -  [C0402_1]  165.77 32.93 90 top
C559  -  [C0402_1]  163.1 19.08 270 top
C563  -  [C0402_1]  150.15 12.22 270 top
C564  -  [C0603_1]  128.05 30.89 270 top
C571  -  [C0402_1]  101.63 84.74 180 top
C572  -  [C0805_1]  101.63 83.22 0 top
C573  -  [C0603_1]  103.03 95.16 90 top
C574  -  [C0402_1]  96.68 96.68 180 top
C575  -  [C0805_1]  84.36 69.25 270 top
C576  -  [C0402_1]  106.2 101.25 0 top
C577  -  [C0805_1]  82.33 69.25 270 top
C578  -  [C0603_1]  96.81 106.33 180 top
C579  -  [C0603_1]  99.98 112.3 270 top
C580  -  [C0402_1]  99.35 109.63 90 top
C581  -  [C0805_1]  91.35 101.76 0 top
C582  -  [C0805_1]  91.35 103.79 0 top
C583  -  [C0402_1]  86.39 58.71 90 top
C584  -  [C0402_1]  79.28 61.5 180 top
C585  -  [C0805_1]  82.84 58.96 0 top
C586  -  [C0805_1]  82.84 56.55 0 top
C587  -  [C0805_1]  72.42 69.63 90 top
C588  -  [C0805_1]  76.23 69.63 90 top
C589  -  [C0805_1]  74.33 69.63 90 top
C590  -  [C0603_1]  70.77 69.5 270 top
C591  -  [C0402_1]  83.47 62.77 90 top
C592  -  [C0402_1]  85 63.28 180 top
C593  -  [C0805_1]  135.29 17.43 0 top
C594  -  [C0603_1]  134.02 23.15 0 top
C595  -  [C0805_1]  108.64 17.3 270 top
C596  -  [C0805_1]  138.46 20.35 270 top
C597  -  [C0402_1]  124.49 30.64 90 top
C598  -  [C0402_1]  117.38 29.88 90 top
C599  -  [C0805_1]  110.62 17.3 270 top
C600  -  [C0603_1]  120.56 27.85 0 top
C601  -  [C0805_1]  123.48 18.83 270 top
C602  -  [C0402_1]  125.89 22 90 top
C603  -  [C0805_1]  125.64 18.83 270 top
C604  -  [C0603_1]  123.22 22 90 top
C605  -  [C0603_1]  99.6 198.28 270 top
C606  -  [C0402_1]  99.6 203.68 90 top
C607  -  [C0402_1]  8.85 147.94 0 top
C608  -  [C0603_1]  5.11 153.7 180 top
C609  -  [C0805_1]  102.52 199.42 180 top
C610  -  [C0603_1]  99.6 201.2 270 top
C611  -  [C0603_1]  104.93 199.04 270 top
C612  -  [C0805_1]  99.6 185.58 180 top
C613  -  [C0402_1]  64.68 69.37 90 top
C624  -  [C0402_1]  125.71 15.78 90 top
C625  -  [C0402_1]  126.83 15.78 90 top
C652  -  [C0402_1]  69.76 151.67 180 top
C653  -  [C0402_1]  69.76 152.81 180 top
C654  -  [C0402_1]  64.78 99.27 270 top
C659  -  [C0402_1]  20.1 89.82 180 top
C660  -  [C0402_1]  27.11 105.59 0 top
C663  -  [C0402_1]  15.65 102.27 90 top
C664  -  [C0402_1]  17.18 89.24 0 top
C666  -  [C0402_1]  9.94 203.74 0 top
C668  -  [C0402_1]  36.74 120.17 90 top
C669  -  [C0805_1]  72.17 226.85 270 top
C670  -  [C0402_1]  59.98 208.06 0 top
C671  -  [C0805_1]  149.51 58.07 270 top
C672  -  [C0805_1]  138.77 36.48 180 top
C673  -  [C0805_1]  221.42 59.11 180 top
C674  -  [C0805_1]  221.42 57.06 180 top
C675  -  [C0402_1]  170.29 218.35 90 top
C676  -  [C0603_1]  171.48 218.68 90 top
C677  -  [C0402_1]  6.38 162.97 180 top
C678  -  [C0402_1]  210.54 13.11 270 top
C679  -  [C0402_1]  41.21 61.65 180 top
C680  -  [C0402_1]  204.12 140.49 180 top
C681  -  [C0402_1]  29.88 95.66 180 top
C682  -  [C0603_1]  10.59 168.51 270 top
C683  -  [C0402_1]  90.46 18.32 90 top
C684  -  [C0402_1]  88.5 5.8 270 top
C685  -  [C0402_1]  104.43 12.86 90 top
C686  -  [C0402_1]  106.4 5.87 270 top
C689  -  [C0402_1]  213.21 35.34 180 top
C690  -  [C0402_1]  22.33 70.01 0 top
C691  -  [C0402_1]  20.1 68.87 0 top
C696  -  [C0402_1]  185.58 7.4 90 top
C697  -  [C0402_1]  54.9 68.74 270 top
C698  -  [C0402_1]  56.52 68.74 270 top
C699  -  [C0402_1]  100.11 217.58 270 top
C700  -  [C0402_1]  222.28 225.08 90 top
C701  -  [C0402_1]  193.83 204.76 180 top
C702  -  [C0402_1]  193.83 205.9 180 top
C703  -  [C0402_1]  192.44 222.28 0 top
C704  -  [C0402_1]  169.2 201.96 0 top
C705  -  [C0603_1]  169.07 218.73 270 top
C706  -  [C0402_1]  167.29 217.46 180 top
C707  -  [C0402_1]  167.22 221.75 90 top
C708  -  [C0402_1]  165.01 222.16 180 top
C709  -  [C0402_1]  162.85 222.16 180 top
C710  -  [C0402_1]  168.56 221.77 90 top
C711  -  [C0402_1]  201.84 13.49 270 top
C722  -  [C0402_1]  9.94 206.66 0 top
C723  -  [C0402_1]  128.3 3.84 180 top
C724  -  [C0402_1]  119.29 3.84 180 top
C725  -  [C0402_1]  125.76 3.84 0 top
C726  -  [C0402_1]  43.34 25.81 270 top
C727  -  [C0402_1]  113.21 15.83 90 top
C728  -  [C0402_1]  121.83 15.65 90 top
C729  -  [C0603_1]  226.22 191.04 90 top
C730  -  [C0603_1]  222.03 187.74 0 top
C731  -  [C0603_1]  227.74 191.04 270 top
C732  -  [C0805_1]  222.03 189.39 0 top
C733  -  [C0805_1]  166.15 187.74 270 top
C734  -  [C0805_1]  168.18 187.74 270 top
C735  -  [C0603_1]  237.27 149.89 0 top
C736  -  [C0402_1]  223.55 153.19 180 top
C737  -  [C0402_1]  220.5 145.07 180 top
C738  -  [C0603_1]  228.89 157.77 270 top
C739  -  [C0603_1]  237.52 160.69 270 top
C740  -  [C0402_1]  152.58 176 180 top
C741  -  [C0402_1]  211.87 157.39 90 top
C742  -  [C0603_1]  233.46 160.69 270 top
C743  -  [C0805_1]  184.44 185.96 270 top
C744  -  [C0805_1]  186.47 185.96 270 top
C745  -  [C0402_1]  226.6 140.88 0 top
C746  -  [C0402_1]  226.6 145.45 180 top
C747  -  [C0402_1]  231.05 140.88 180 top
C748  -  [C0402_1]  226.55 143.21 180 top
C749  -  [C0402_1]  231.05 143.16 180 top
C750  -  [C0603_1]  224.31 160.69 180 top
C751  -  [C0402_1]  226.6 144.3 180 top
C752  -  [C0402_1]  228.89 145.45 0 top
C753  -  [C0402_1]  173.51 175.8 270 top
C754  -  [C0402_1]  233.78 143.16 180 top
C755  -  [C0402_1]  215.3 157.39 90 top
C756  -  [C0402_1]  234.22 138.59 270 top
C757  -  [C0402_1]  233.78 145.57 0 top
C758  -  [C0805_1]  217.08 185.45 0 top
C759  -  [C0805_1]  217.08 183.29 0 top
C760  -  [C0402_1]  222.66 142.4 270 top
C761  -  [C0603_1]  237.27 148.62 180 top
C762  -  [C0402_1]  237.65 147.35 180 top
C763  -  [C0402_1]  233.2 148.75 180 top
C764  -  [C0603_1]  237.27 146.08 180 top
C765  -  [C0402_1]  227.62 171.23 0 top
C766  -  [C0402_1]  235.36 144.51 270 top
C767  -  [C0402_1]  218.73 157.39 90 top
C768  -  [C0603_1]  144.69 181.26 0 top
C769  -  [C0805_1]  173.26 185.96 270 top
C770  -  [C0805_1]  146.59 189.39 270 top
C771  -  [C0603_1]  149.7 186.79 90 top
C772  -  [C0402_1]  133.66 175.83 180 top
C773  -  [C0402_1]  227.11 122.71 180 top
C774  -  [C0402_1]  227.11 118.27 0 top
C775  -  [C0402_1]  208.44 157.39 90 top
C776  -  [C0603_1]  88.17 25.94 270 top
C777  -  [C0603_1]  75.47 28.1 180 top
C778  -  [C0603_1]  47.91 35.59 0 top
C779  -  [C0603_1]  67.83 20.89 90 top
C780  -  [C0805_1]  69.5 20.86 270 top
C781  -  [C0603_1]  45.5 28.86 90 top
C782  -  [C0603_1]  46.83 28.86 90 top
C783  -  [C0603_1]  47.85 31.53 0 top
C784  -  [C0603_1]  51.98 27.34 90 top
C785  -  [C0805_1]  69.76 6.89 0 top
C786  -  [C0805_1]  69.76 8.92 0 top
C787  -  [C0402_1]  70.01 10.45 0 top
C788  -  [C0402_1]  45.24 13.75 0 top
C789  -  [C0402_1]  57.56 33.05 0 top
C790  -  [C0402_1]  54.52 29.62 270 top
C791  -  [C0402_1]  58.33 28.48 180 top
C792  -  [C0402_1]  58.2 31.91 180 top
C793  -  [C0402_1]  56.55 31.4 90 top
C794  -  [C0603_1]  52.69 40.29 270 top
C795  -  [C0603_1]  71.79 39.91 270 top
C796  -  [C0805_1]  62.77 33.31 180 top
C797  -  [C0402_1]  57.56 34.07 0 top
C798  -  [C0805_1]  44.36 53.44 90 top
C799  -  [C0805_1]  44.36 47.91 270 top
C800  -  [C0402_1]  75.22 49.31 180 top
C801  -  [C0402_1]  58.71 38.77 180 top
C802  -  [C0402_1]  58.71 35.21 180 top
C803  -  [C0402_1]  56.55 38.39 180 top
C804  -  [C0402_1]  57.06 35.72 270 top
C805  -  [C0805_1]  61.75 28.35 90 top
C806  -  [C0805_1]  75.6 39.91 90 top
C807  -  [C0402_1]  206.28 213.14 180 top
C808  -  [C0402_1]  206.28 211.36 0 top
C809  -  [C0402_1]  186.65 7.4 90 top
C810  -  [C0402_1]  196.88 213.14 0 top
C811  -  [C0805_1]  104.87 6.2 90 top
C812  -  [C0805_1]  90.08 6.13 90 top
C813  -  [C0805_1]  95.41 23.65 90 top
C814  -  [C0805_1]  230.28 222.54 90 top
C815  -  [C0402_1]  214.66 12.99 270 top
C816  -  [C0402_1]  154.21 189.2 90 top
C817  -  [C0402_1]  7.02 143.03 90 top
C818  -  [C0402_1]  229.2 27.97 270 top
C819  -  [C0402_1]  234.6 32.04 270 top
C820  -  [C0402_1]  198.03 153.45 270 top
C821  -  [C0402_1]  58.78 64.47 90 top
C822  -  [C0805_1]  73.57 39.91 90 top
C823  -  [C0402_1]  65.18 236.51 270 top
C824  -  [C0402_1]  62.64 238.67 270 top
C825  -  [C0603_1]  223.55 225.33 90 top
C826  -  [C0603_1]  196.43 221.27 90 top
C827  -  [C0402_1]  140.37 26.32 270 top
C828  -  [C0402_1]  141.26 5.37 270 top
C829  -  [C0402_1]  93.38 94.77 0 top
C830  -  [C0402_1]  98.33 96.04 270 top
C831  -  [C0402_1]  97.19 93.89 90 top
C832  -  [C0402_1]  102.14 107.98 180 top
C833  -  [C0402_1]  102.14 106.84 180 top
C834  -  [C0402_1]  102.14 110.27 180 top
C835  -  [C0402_1]  80.93 50.71 270 top
C836  -  [C0402_1]  121.83 17.81 90 top
C838  -  [C0603_1]  198.66 139.35 180 top
C839  -  [C0402_1]  24.67 16.54 180 top
C840  -  [C0402_1]  24.67 17.69 180 top
C841  -  [C0402_1]  24.67 20.35 180 top
C842  -  [C0402_1]  24.67 21.5 180 top
C843  -  [C0805_1]  18.19 230.03 90 top
C844  -  [C0402_1]  52.1 121.32 270 top
C845  -  [C0402_1]  194.85 4.48 0 top
C846  -  [C0402_1]  17.13 92.49 0 top
C848  -  [C0402_1]  71.91 173.39 90 top
C849  -  [C0402_1]  70.9 167.93 90 top
C850  -  [C0402_1]  68.87 160.56 90 top
C851  -  [C0402_1]  66.96 162.72 0 top
C854  -  [C0402_1]  189.14 14.64 90 top
C855  -  [C0603_1]  9.81 44.74 0 top
C856  -  [C0402_1]  20.1 205.58 0 top
C857  -  [C0402_1]  20.1 204.19 180 top
C858  -  [C0402_1]  48.17 39.02 270 top
C_INTRUSION  -  [J2X1]  8.4 168.64 90 top
CLR_CMOS  -  [J3X1]  4.6 67.72 270 top
CMK1  -  [WCM2012F2S_1]  208.82 218.14 90 top
CMK2  -  [WCM2012F2S_1]  210.47 218.14 90 top
CMK3  -  [WCM2012F2S_1]  212.83 218.19 90 top
CMK4  -  [WCM2012F2S_1]  214.46 218.19 90 top
CMK9  -  [CMM21_1]  173.18 217.96 0 top
CMK10  -  [CMM21_1]  177.12 217.96 0 top
CMK11  -  [CMM21_1]  174.86 217.96 0 top
CMK12  -  [CMM21_1]  178.8 217.96 0 top
CMK13  -  [CMM21_1]  11.59 113.19 180 top
CMK14  -  [CMM21_1]  13.37 113.19 180 top
CMK15  -  [CMM21_1]  11.97 97.95 0 top
CMK16  -  [CMM21_1]  10.19 97.95 0 top
CMK17  -  [CMM21_1]  133.89 213.01 180 top
CMK18  -  [CMM21_1]  135.67 213.01 180 top
CMK19  -  [CMM21_1]  129.7 212.88 180 top
CMK20  -  [CMM21_1]  127.92 212.88 180 top
CMK21  -  [CMM21_1]  29.75 54.26 270 top
CMK22  -  [CMM21_1]  29.75 58.2 270 top
CMK23  -  [CMM21_1]  29.75 50.2 270 top
CMK24  -  [CMM21_1]  29.75 59.98 270 top
CMK25  -  [CMM21_1]  29.75 56.04 270 top
CMK26  -  [CMM21_1]  29.75 51.98 270 top
CMK27  -  [CMM21_1]  95.03 214.03 90 top
CMK28  -  [CMM21_1]  95.03 212.25 90 top
CMK29  -  [CMM21_1]  116.11 212 180 top
CMK30  -  [CMM21_1]  110.52 212 180 top
CMK31  -  [CMM21_1]  114.33 212 180 top
CMK32  -  [CMM21_1]  112.3 212 180 top
CMK33  -  [WCM2012F2S_1]  181.13 224.44 90 top
CMK34  -  [WCM2012F2S_1]  182.91 224.44 90 top
CMK35  -  [WCM2012F2S_1]  184.82 224.44 90 top
CMK36  -  [WCM2012F2S_1]  186.6 224.44 90 top
CMK37  -  [CMM21_R0402]  12.61 130.84 270 top
CN1  -  [8P4C]  179.23 10.19 0 top
CN2  -  [8P4C]  161.45 10.19 0 top
CN3  -  [8P4C]  169.96 10.19 0 top
CN4  -  [8P4C]  154.21 10.19 0 top
CN5  -  [8P4C]  199.42 221.01 180 top
CN6  -  [8P4C]  203.74 221.01 180 top
CN7  -  [8P4C]  11.06 18.52 270 top
CN8  -  [8P4C]  11.06 14.41 270 top
CODEC  -  [LQFP48]  18.45 221.14 90 top
COM1  -  [D-SUB_9P-KORTAK_1]  204.4 228.88 0 top
COM2  -  [J5X2_COM]  6.1 17.79 270 top
CPU1  -  [LGA1150_HSW_SKT-INTEL_1]  159.52 127.03 0 top
CPU_FAN  -  [FAN4X1]  237.27 92.87 90 top
D1  -  [BAT54_132_2]  234.35 48.04 270 top
D2  -  [FPC_4P10_R_1]  26.07 55.15 90 top
D3  -  [FPC_4P10_R_1]  26.19 51.09 90 top
D5  -  [1N4148]  236 103.54 0 top
D6  -  [1N4148]  125.64 188.88 90 top
D7  -  [1N4148]  227.74 107.09 90 top
D8  -  [BAT54_132_2]  13.25 171.38 90 top
D9  -  [BAV99_132_2]  13.19 45.02 90 top
D11  -  [1N4148]  183.93 11.53 90 top
D14  -  [SOD_123_2]  200.95 203.99 90 top
D15  -  [SOD_123_2]  198.79 203.99 90 top
D16  -  [FPC_4P10_R_1]  115.22 215.3 180 top
D17  -  [FPC_4P10_R_1]  111.41 215.3 0 top
D18  -  [BAT54_132_2]  14.26 230.28 180 top
D19  -  [SOD_523]  12.73 209.07 90 top
D20  -  [BAT54_132_2]  158.27 22.26 0 top
D21  -  [BAT54_132_2]  158.27 17.56 270 top
D22  -  [SOT23_RAC_Z_2]  104.81 115.86 0 top
D23  -  [BAT54_132_2]  92.11 184.69 0 top
D24  -  [SOT23_3L]  87.03 226.6 0 top
D25  -  [SOT23_3L]  87.03 222.28 0 top
D27  -  [SOT23_3L]  8.16 210.34 0 top
D28  -  [SOT23_3L]  4.73 210.34 0 top
D29  +  [SOD_123_2]  206.28 216.31 90 top
D30  +  [SOD_123_2]  196.88 216.57 270 top
D31  +  [SOD_123_2]  4.1 29.5 270 top
D32  +  [SOD_123_2]  196.88 209.96 270 top
D34  -  [BAV99_132_2]  12.86 205.65 0 top
D35  -  [SOD_523]  108.97 215.03 90 top
D36  -  [SOD_523]  105.59 214.98 90 top
D37  -  [SOD_523]  118.27 214.92 90 top
D38  -  [SOD_523]  98.33 217.46 270 top
D39  -  [SOD_523]  127.54 207.93 180 top
D40  -  [BAV99_132_2]  5.37 35.59 270 top
DIMM1  -  [DDR3_240P_2]  220.93 42.6 270 top
DIMM2  -  [DDR3_240P_2]  220.93 65.12 270 top
DIMM3  -  [DDR3_240P_2]  220.93 52.92 270 top
DIMM4  -  [DDR3_240P_2]  220.93 72.89 270 top
DP1  -  [CONN_DISPLAYPORT_19P_1]  216.5 233.46 180 top
DP2  -  [CONN_DISPLAYPORT_19P_1]  192.3 233.46 180 top
DVI-D  -  [DVI_29P_MB_2]  161.86 242.79 0 top
EC1  -  [EC3D5_8_H11MM_1P]  71.15 196.37 270 top
EC2  -  [EC3D5_8_H11D5MM_1P]  71.41 187.61 270 top
EC3  -  [EC3D5_8_H11MM_1P]  31.66 196.12 270 top
EC4  -  [EC3D5_8_H11D5MM_1P]  31.66 186.98 270 top
EC5  -  [EC2D5_6D3_H11MM]  51.21 194.34 270 top
EC6  +  [EC3D5_8_H11D5MM_1P]  51.47 186.72 270 top
EC7  -  [EC2D5_6D3_H11MM]  6.51 126.27 270 top
EC8  -  [EC2D5_6D3_H11MM]  7.4 102.52 270 top
EC9  -  [EC2D5_6D3_H11MM]  136.99 207.42 0 top
EC10  -  [EC2D5_6D3_H11MM]  145.45 219.23 0 top
EC11  -  [EC2D5_6D3_H11MM]  18.96 33.69 270 top
EC12  -  [EC2D5_6D3_H11MM]  236.51 108.44 0 top
EC13  -  [EC2D5_6D3_H11MM]  108.47 178.72 0 top
EC14  -  [EC2D5_6D3_H11MM]  123.48 212.76 0 top
EC15  -  [EC2D5_6D3_H11MM]  6.51 225.08 0 top
EC16  -  [EC2D5_6D3_H11MM]  6.51 218.22 0 top
EC17  -  [EC2D5_6D3_H11MM]  29.37 221.27 0 top
EC18  -  [EC2D5_6D3_H11MM]  36.61 221.27 0 top
EC19  -  [EC2D5_6D3_H11MM]  96.81 33.81 0 top
EC20  -  [EC2D5_6D3_H8MM]  185.07 33.94 0 top
EC21  -  [EC2D5_6D3_H8MM]  185.07 26.96 0 top
EC22  -  [EC2D5_6D3_H8MM]  133.38 31.66 0 top
EC23  -  [EC2D5_6D3_H8MM]  140.49 31.66 0 top
EC24  -  [EC2D5_6D3_H8MM]  170.09 86.39 270 top
EC25  -  [EC2D5_6D3_H11MM]  147.1 20.23 0 top
EC27  +  [EC2D5_6D3_H8MM]  94.9 81.06 0 top
EC28  -  [EC2D5_6D3_H11MM]  116.24 25.43 0 top
EC29  -  [EC2D5_6D3_H11MM]  109.25 25.43 0 top
EC30  -  [EC2D5_6D3_H11MM]  96.68 207.55 0 top
EC42  -  [EC2D5_6D3_H8MM]  158.71 86.39 270 top
EC45  +  [EC2D5_6D3_H11MM]  130.08 20.1 0 top
EC46  +  [EC3D5_8_H11D5MM_1P]  171.74 193.45 0 top
EC47  +  [EC3D5_8_H11D5MM_1P]  205.65 184.06 0 top
EC48  +  [EC3D5_8_H11D5MM_1P]  187.1 193.45 0 top
EC49  +  [EC2D5_6D3_H8MM]  181.64 163.35 0 top
EC50  +  [EC2D5_6D3_H8MM]  201.96 156.5 0 top
EC51  +  [EC2D5_6D3_H8MM]  170.59 163.35 0 top
EC52  +  [EC2D5_6D3_H8MM]  163.48 163.35 0 top
EC53  +  [EC2D5_6D3_H8MM]  152.05 163.35 0 top
EC54  +  [EC2D5_6D3_H8MM]  144.94 163.35 0 top
EC55  +  [EC2D5_6D3_H8MM]  136.81 163.35 0 top
EC56  +  [EC3D5_8_H12MM_1P]  74.96 33.69 0 top
EC57  +  [EC2D5_6D3_H8MM]  71.53 14.64 0 top
EC58  +  [EC3D5_8_H12MM_1P]  67.72 28.99 0 top
EC59  +  [EC2D5_6D3_H8MM]  49.56 47.35 0 top
EC60  +  [EC2D5_6D3_H11MM]  11.21 141.76 270 top
EC61  +  [EC3D5_8_H12MM_1P]  74.84 22.26 0 top
F1  -  [FUSE_SMD_1]  227.24 210.34 90 top
F5  -  [F1812]  176.05 204.25 180 top
F_AUDIO  -  [J5X2_AUDIO_1]  6.13 201.58 270 top
F_PANEL  -  [J7X2_PANEL_10P]  5.7 46.39 270 top
F_USB1  -  [J5X2_USB_1394]  6 114.21 270 top
F_USB2  -  [J5X2_USB_1394]  6 90.84 270 top
F_USB3  -  [J5X1_CR]  4.48 137.57 270 top
FB1  -  [FB0603_1]  152.94 214.15 0 top
FB2  -  [FB0603_1]  153.19 216.69 180 top
FB3  -  [FB0603_1]  155.86 214.15 0 top
FB4  -  [FB0603_1]  156.12 216.69 0 top
FB5  -  [FB0603_1]  158.73 214.15 0 top
FB6  -  [FB0603_1]  159.04 216.69 0 top
FB7  -  [FB0603_1]  236.13 220.63 90 top
FB8  -  [FB0603_1]  234.73 220.63 90 top
FB9  -  [FB0603_1]  233.33 220.63 90 top
FB10  -  [FB0603_1]  231.93 220.63 90 top
FB13  -  [FB0603_1]  70.01 237.78 0 top
FB14  -  [FB0603_1]  82.96 223.93 270 top
FB15  -  [FB0603_1]  87.79 239.55 270 top
FB16  -  [FB0603_1]  70.14 240.32 0 top
FB17  -  [FB0603_1]  240.19 27.46 270 top
FW_DEBUG  -  [J2X1]  199.85 35.11 0 top
H1  -  [HOLE8_5]  34.45 233.84 0 top
H2  -  [HOLE8_5]  80.17 233.84 0 top
H3  -  [HOLE8_5]  237.65 210.98 0 top
H4  -  [HOLE8_5]  14.13 78.9 0 top
H5  -  [HOLE8_5]  80.17 78.9 0 top
H6  -  [HOLE8_5]  237.65 78.9 0 top
H7  -  [HOLE8_5]  80.17 6.51 0 top
H8  -  [HOLE8_5]  237.65 6.5 0 top
ILAN  -  [QFN48_PT04_3X3]  71.91 215.02 90 top
INT_SPK  -  [J4X2_4P]  6.13 187.61 270 top
L1  -  [CHOKE_4R7K_PT3D35MM_SMD]  72.3 207.3 0 top
L2  -  [CHOKE_2R2N_SMD_2P]  63.47 224.57 0 top
L3  -  [CHOKE_9D5X11_PT7MM_H_2]  193.07 30.77 90 top
L4  -  [CHOKE_1R0M-R_1]  152.81 30 180 top
L5  -  [FB0805_1]  81.19 53.88 90 top
L6  -  [CHOKE_4R7_PT2D65MM_SMD]  74.71 65.44 90 top
L7  -  [CHOKE_9D5X11_PT7MM_H_2]  221.39 195.74 180 top
L8  -  [CHOKE-R36M_PT6D6X4D2MM_R]  165.39 174.15 90 top
L9  -  [CHOKE-R36M_PT6D6X4D2MM_R]  186.21 174.15 90 top
L10  -  [CHOKE-R36M_PT6D6X4D2MM_R]  212.76 169.32 0 top
L11  -  [CHOKE-R36M_PT6D6X4D2MM_R]  146.34 174.15 90 top
L12  -  [CHOKE_9D5X11_PT7MM_H_2]  82.46 27.97 180 top
L13  -  [CHOKE_2R0M_PT8X6D8MM]  60.61 10.19 0 top
L14  -  [CHOKE_2R0M_PT8X6D8MM]  60.42 49.18 180 top
LPT  -  [J13X2_LPT_1]  168.43 5.89 0 top
ME_DISABLE  -  [J3X1]  4.6 78.01 270 top
ME_TEST  -  [J3X2]  5.7 158.48 270 top
MN1  -  [SOT23_GDS_2]  163.48 204.5 0 top
MN2  -  [SOT23_GDS_2]  159.8 204.5 0 top
NOREF  -  [unnamed]  239.4 12.53 0 top
NOREF#2  -  [#2]  99.09 160.03 270 top
NOREF#3  -  [unnamed]  5.08 5.08 0 top
NOREF#4  -  [#2]  244 244 270 top
NOREF#5  -  [#2]  63.99 181.06 0 top
NOREF#6  -  [#2]  269.78 310.8 0 top
NOREF#7  -  [#2]  244 244 0 top
NOREF#8  -  [#2]  244 244 270 top
NOREF#9  -  [#2]  95.4 109.37 90 top
NOREF#10  -  [#2]  195.23 183.55 270 top
NOREF#11  -  [#2]  105.55 138.76 270 top
NOREF#12  -  [#2]  98.33 136.05 270 top
NOREF#13  -  [#2]  167.02 81.59 0 top
NOREF#14  -  [#2]  100.24 149.89 270 top
NOREF#15  -  [#2]  151.3 304.96 0 top
NOREF#16  -  [#2]  134.96 142.22 270 top
NOREF#17  -  [#2]  132.62 123.12 0 top
NOREF#18  -  [#2]  291.45 325.69 0 top
NOREF#19  -  [#2]  107.25 156.32 270 top
NOREF#20  -  [unnamed]  39.02 238.54 0 top
NOREF#21  -  [#2]  103.64 131.05 270 top
NOREF#22  -  [#2]  96.5 179.38 270 top
NOREF#23  -  [unnamed]  5.08 238.92 0 top
NOREF#24  -  [#2]  83.6 17.05 0 top
NOREF#25  -  [#2]  98.97 167.55 270 top
NOREF#26  -  [unnamed]  238.73 217.33 0 top
NOREF#27  -  [unnamed]  238.73 217.33 180 bottom
NOREF#28  -  [unnamed]  8.03 236.13 180 bottom
NOREF#29  -  [unnamed]  239.31 12.96 180 bottom
OBR  -  [J2X1]  12.73 68.49 180 top
P1  -  [SHORT2-NMNP]  165.39 175.29 90 top
P2  -  [SHORT2-NMNP]  165.51 173.13 270 top
P3  -  [SHORT2-NMNP]  185.71 175.29 90 top
P4  -  [SHORT2-NMNP]  185.71 173.26 270 top
P5  -  [SHORT2-NMNP]  213.77 170.34 45 top
P6  -  [SHORT2-NMNP]  211.87 168.69 225 top
P7  -  [SHORT2-NMNP]  146.21 175.17 90 top
P8  -  [SHORT2-NMNP]  146.21 173.26 270 top
P9  -  [SHORT2-NMNP]  62.01 9.3 135 top
P10  -  [SHORT2-NMNP]  60.23 10.95 315 top
P11  -  [SHORT2-NMNP]  61.25 48.67 135 top
P12  -  [SHORT2-NMNP]  59.47 50.32 315 top
PCH1  -  [BGA708_LYNX-INTEL]  46.64 96.81 270 top
PCI  -  [PCI_120P-AB]  41.11 163.98 270 top
PCIE1X  -  [PCIE_X1_36P_2]  61.43 186.9 0 top
PCIE16X_1  -  [PCIE_X16_164P_4]  81.75 186.9 0 top
PCIE16X_2  -  [PCIE_X16_164P_4]  20.78 186.9 0 top
PFB1  -  [FB0603_1]  40.42 117.38 90 top
PFB2  -  [FB0805_1]  48.42 122.84 180 top
PFB4  -  [FB0603_1]  74.2 140.49 90 top
PFB5  -  [FB0603_1]  71.79 142.78 0 top
PFB6  -  [FB0603_1]  72.42 146.26 0 top
PFB7  -  [FB0603_1]  61.25 163.74 270 top
